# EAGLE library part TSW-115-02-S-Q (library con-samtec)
THROUGH-HOLE .025" SQ POST HEADER Source: Samtec TSW.pdf
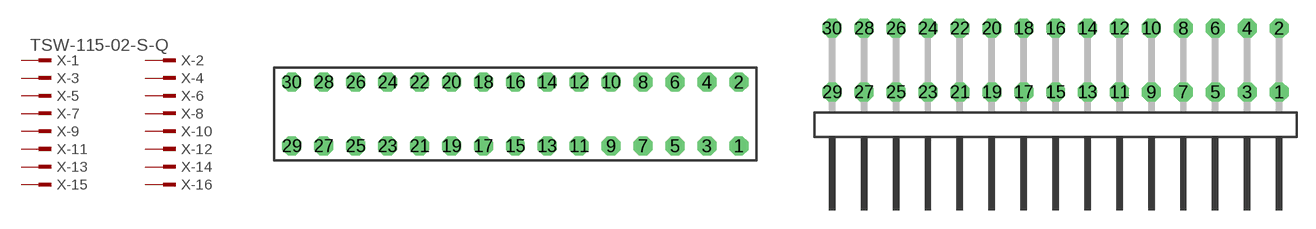
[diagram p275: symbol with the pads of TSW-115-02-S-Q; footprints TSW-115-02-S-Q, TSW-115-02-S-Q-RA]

Designator prefix X; gates -1=MPINV -2=MPIN -3=MPIN -4=MPIN -5=MPIN -6=MPIN -7=MPIN -8=MPIN -9=MPIN -10=MPIN -11=MPIN -12=MPIN -13=MPIN -14=MPIN -15=MPIN -16=MPIN -17=MPIN -18=MPIN -19=MPIN -20=MPIN -21=MPIN -22=MPIN -23=MPIN -24=MPIN -25=MPIN -26=MPIN -27=MPIN -28=MPIN -29=MPIN -30=MPIN

## TSW-115-02-S-Q (OC_FARNELL: unknown; OC_NEWARK: unknown)  [TSW-115-02-S-Q]
1  -1:1  pas
2  -2:1  pas
3  -3:1  pas
4  -4:1  pas
5  -5:1  pas
6  -6:1  pas
7  -7:1  pas
8  -8:1  pas
9  -9:1  pas
10  -10:1  pas
11  -11:1  pas
12  -12:1  pas
13  -13:1  pas
14  -14:1  pas
15  -15:1  pas
16  -16:1  pas
17  -17:1  pas
18  -18:1  pas
19  -19:1  pas
20  -20:1  pas
21  -21:1  pas
22  -22:1  pas
23  -23:1  pas
24  -24:1  pas
25  -25:1  pas
26  -26:1  pas
27  -27:1  pas
28  -28:1  pas
29  -29:1  pas
30  -30:1  pas

## TSW-115-02-S-Q-RA (OC_FARNELL: unknown; OC_NEWARK: unknown)  [TSW-115-02-S-Q-RA]
Pads as for TSW-115-02-S-Q

## Footprint TSW-115-02-S-Q (pad centres in mm)
THROUGH-HOLE .025" SQ POST HEADER Source: Samtec TSW.pdf
drill 1 pad 1.5 octagon: 1 17.78,-2.54; 2 17.78,2.54; 3 15.24,-2.54; 4 15.24,2.54; 5 12.7,-2.54; 6 12.7,2.54; 7 10.16,-2.54; 8 10.16,2.54; 9 7.62,-2.54; 10 7.62,2.54; 11 5.08,-2.54; 12 5.08,2.54; 13 2.54,-2.54; 14 2.54,2.54; 15 0,-2.54; 16 0,2.54; 17 -2.54,-2.54; 18 -2.54,2.54; 19 -5.08,-2.54; 20 -5.08,2.54; 21 -7.62,-2.54; 22 -7.62,2.54; 23 -10.16,-2.54; 24 -10.16,2.54; 25 -12.7,-2.54; 26 -12.7,2.54; 27 -15.24,-2.54; 28 -15.24,2.54; 29 -17.78,-2.54; 30 -17.78,2.54

## Footprint TSW-115-02-S-Q-RA (pad centres in mm)
THROUGH-HOLE .025" SQ POST HEADER Source: Samtec TSW.pdf
drill 1 pad 1.5 octagon: 1 17.78,1.524; 2 17.78,6.604; 3 15.24,1.524; 4 15.24,6.604; 5 12.7,1.524; 6 12.7,6.604; 7 10.16,1.524; 8 10.16,6.604; 9 7.62,1.524; 10 7.62,6.604; 11 5.08,1.524; 12 5.08,6.604; 13 2.54,1.524; 14 2.54,6.604; 15 0,1.524; 16 0,6.604; 17 -2.54,1.524; 18 -2.54,6.604; 19 -5.08,1.524; 20 -5.08,6.604; 21 -7.62,1.524; 22 -7.62,6.604; 23 -10.16,1.524; 24 -10.16,6.604; 25 -12.7,1.524; 26 -12.7,6.604; 27 -15.24,1.524; 28 -15.24,6.604; 29 -17.78,1.524; 30 -17.78,6.604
